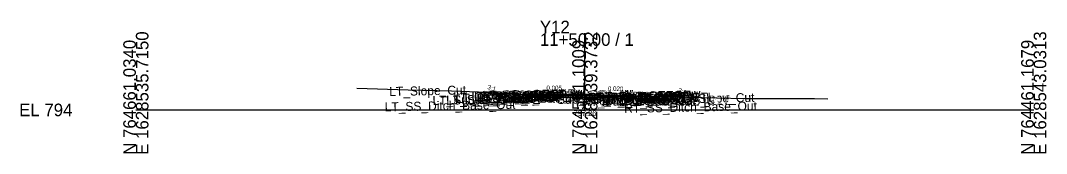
# Model space of a CAD drawing. Extents: x -26 to 203, y -10 to 3521.
# Drawn here: x -25.7 to 202.8, y 2990.3 to 3019.9 of the extents above; entities that cross this region are included whole.
import ezdxf

# ---------------------------------------------------------------- set-up
doc = ezdxf.new("R2010")
doc.units = 0
for name, color, linetype in [('Default', 7, 'Continuous'), ('Exist Cross Section Cell', 7, 'Continuous'), ('Exist XS Center Line Elevation Label', 7, 'Continuous'), ('Exist XS Ground Line', 7, 'Continuous'), ('Prop CMT Conc Surface', 7, 'Continuous'), ('Prop CMT Concrete Structures', 7, 'Continuous'), ('Prop CMT Pvmt Course 1', 7, 'Continuous'), ('Prop CMT Pvmt Course 2', 7, 'Continuous'), ('Prop CMT Pvmt Course 3', 7, 'Continuous'), ('Prop CMT Pvmt Surface', 7, 'Continuous'), ('Prop CMT Pvmt Wedge Surface 1', 7, 'Continuous'), ('Prop CMT Pvmt Wedge Surface 2', 7, 'Continuous'), ('Prop CMT Pvmt Wedge Surface 3', 7, 'Continuous'), ('Prop CMT Shld Paved Course 3', 7, 'Continuous'), ('Prop CMT Slope Grass', 7, 'Continuous'), ('Prop CMT Subgrade Earthwork', 7, 'Continuous'), ('Prop XS SE Text', 7, 'Continuous'), ('Prop XS Side Slope Text', 7, 'Continuous'), ('Scratch_Level_0', 7, 'Continuous')]:
    doc.layers.add(name, color=color, linetype=linetype)

msp = doc.modelspace()

# ---------------------------------------------------------------- linework, layer by layer
at = {"layer": 'Exist Cross Section Cell'}
for p, q in [((100, 3000), (100, 3017.06)), ((0, 3000), (100, 3000)), ((100, 3000), (200, 3000))]:
    msp.add_line(p, q, dxfattribs=at)
at = {"layer": 'Exist XS Ground Line'}
msp.add_lwpolyline([(49.23, 3004.87), (60.62, 3004.44), (70.29, 3004.23), (76.31, 3004.05), (86.64, 3003.46), (98.59, 3003.29), (100, 3003.26), (113.56, 3003.03), (117.92, 3002.97), (123.03, 3002.85), (135.64, 3002.51), (151.17, 3002.53), (154.14, 3002.48)], dxfattribs=at)
at = {"layer": 'Prop CMT Conc Surface'}
for points in [[(86.35, 3003.43), (85.35, 3003.35), (84.35, 3003.43)], [(113.73, 3003.09), (114.73, 3003), (115.73, 3003.09)]]:
    msp.add_lwpolyline(points, dxfattribs=at)
at = {"layer": 'Prop CMT Concrete Structures'}
for points in [[(86.35, 3003.43), (85.35, 3003.35), (84.35, 3003.43)], [(84.35, 3003.43), (84.35, 3002.85), (86.35, 3002.85)], [(86.35, 3002.85), (86.35, 3003.43)], [(113.73, 3003.09), (114.73, 3003), (115.73, 3003.09)], [(115.73, 3003.09), (115.73, 3002.5), (113.73, 3002.5)], [(113.73, 3002.5), (113.73, 3003.09)]]:
    msp.add_lwpolyline(points, dxfattribs=at)
at = {"layer": 'Prop CMT Pvmt Course 1'}
for points in [[(100, 3003.36), (86.35, 3003.43)], [(86.35, 3003.43), (86.35, 3003.18)], [(86.35, 3003.18), (100, 3003.11)], [(100, 3003.36), (87.35, 3003.43)], [(87.35, 3003.43), (87.35, 3003.3)], [(87.35, 3003.3), (100, 3003.23)], [(100, 3003.23), (100, 3003.36)], [(100, 3003.11), (100, 3003.36)], [(100, 3003.36), (112.73, 3003.11)], [(100, 3003.23), (100, 3003.36)], [(100, 3003.36), (113.73, 3003.09)], [(100, 3003.11), (100, 3003.36)], [(112.73, 3002.98), (100, 3003.23)], [(113.73, 3002.84), (100, 3003.11)], [(112.73, 3003.11), (112.73, 3002.98)], [(113.73, 3003.09), (113.73, 3002.84)]]:
    msp.add_lwpolyline(points, dxfattribs=at)
at = {"layer": 'Prop CMT Pvmt Course 2'}
for points in [[(100, 3003.11), (86.35, 3003.18)], [(86.35, 3003.18), (86.35, 3002.85)], [(100, 3002.78), (100, 3003.11)], [(100, 3002.78), (100, 3003.11)], [(100, 3003.11), (113.73, 3002.84)], [(86.35, 3002.85), (100, 3002.78)], [(113.73, 3002.5), (100, 3002.78)], [(113.73, 3002.84), (113.73, 3002.5)]]:
    msp.add_lwpolyline(points, dxfattribs=at)
at = {"layer": 'Prop CMT Pvmt Course 3'}
msp.add_line((115.73, 3002.5), (116.23, 3002.5), dxfattribs=at)
for points in [[(100, 3002.78), (86.35, 3002.85)], [(86.35, 3002.85), (86.35, 3002.52)], [(86.35, 3002.52), (87.35, 3002.51)], [(100, 3002.44), (100, 3002.78)], [(100, 3002.78), (113.73, 3002.5)], [(100, 3002.44), (100, 3002.78)], [(113.73, 3002.17), (112.73, 3002.19)], [(113.73, 3002.5), (113.73, 3002.17)]]:
    msp.add_lwpolyline(points, dxfattribs=at)
at = {"layer": 'Prop CMT Pvmt Surface'}
for points in [[(100, 3003.36), (86.35, 3003.43)], [(100, 3003.36), (87.35, 3003.43)], [(100, 3003.36), (113.73, 3003.09)], [(100, 3003.36), (112.73, 3003.11)]]:
    msp.add_lwpolyline(points, dxfattribs=at)
at = {"layer": 'Prop CMT Pvmt Wedge Surface 1'}
for points in [[(86.35, 3003.18), (86.35, 3003.43)], [(87.35, 3003.3), (87.35, 3003.43)], [(100, 3003.23), (87.35, 3003.3)], [(100, 3003.23), (112.73, 3002.98)], [(112.73, 3002.98), (112.73, 3003.11)], [(113.73, 3002.84), (113.73, 3003.09)]]:
    msp.add_lwpolyline(points, dxfattribs=at)
at = {"layer": 'Prop CMT Pvmt Wedge Surface 2'}
for points in [[(86.35, 3003.18), (86.35, 3003.43)], [(87.35, 3003.18), (87.35, 3003.43)], [(100, 3003.11), (87.35, 3003.18)], [(100, 3003.11), (100, 3003.36)], [(100, 3003.11), (100, 3003.36)], [(100, 3003.11), (100, 3003.36)], [(100, 3003.11), (100, 3003.36)], [(100, 3003.11), (112.73, 3002.86)], [(112.73, 3002.86), (112.73, 3003.11)], [(113.73, 3002.84), (113.73, 3003.09)]]:
    msp.add_lwpolyline(points, dxfattribs=at)
at = {"layer": 'Prop CMT Pvmt Wedge Surface 3'}
for points in [[(86.35, 3002.85), (86.35, 3003.43)], [(87.35, 3002.84), (87.35, 3003.43)], [(100, 3002.78), (100, 3003.36)], [(100, 3002.78), (100, 3003.36)], [(100, 3002.78), (100, 3003.36)], [(100, 3002.78), (100, 3003.36)], [(112.73, 3002.52), (112.73, 3003.11)], [(113.73, 3002.5), (113.73, 3003.09)], [(100, 3002.78), (87.35, 3002.84)], [(100, 3002.78), (112.73, 3002.52)]]:
    msp.add_lwpolyline(points, dxfattribs=at)
at = {"layer": 'Prop CMT Shld Paved Course 3'}
for p, q in [((83.51, 3002.51), (86.35, 3002.52)), ((116.57, 3002.16), (113.73, 3002.17))]:
    msp.add_line(p, q, dxfattribs=at)
for points in [[(86.35, 3002.85), (84.35, 3002.85), (83.85, 3002.85), (83.51, 3002.51)], [(113.73, 3002.5), (116.23, 3002.5), (116.23, 3002.5), (116.57, 3002.16)]]:
    msp.add_lwpolyline(points, dxfattribs=at)
at = {"layer": 'Prop CMT Slope Grass'}
for points in [[(84.35, 3003.43), (79.35, 3003.53), (78.09, 3003.95)], [(115.73, 3003.09), (120.73, 3003.19), (121.65, 3002.88)]]:
    msp.add_lwpolyline(points, dxfattribs=at)
at = {"layer": 'Prop CMT Subgrade Earthwork'}
for p, q in [((83.51, 3002.51), (82.55, 3003.47)), ((116.57, 3002.16), (117.53, 3003.12)), ((86.35, 3002.52), (83.51, 3002.51)), ((113.73, 3002.17), (116.57, 3002.16))]:
    msp.add_line(p, q, dxfattribs=at)
for points in [[(87.35, 3002.51), (87.37, 3003.45)], [(112.73, 3002.19), (112.71, 3003.05)], [(87.35, 3002.51), (86.35, 3002.52)], [(112.73, 3002.19), (113.73, 3002.17)]]:
    msp.add_lwpolyline(points, dxfattribs=at)

# ---------------------------------------------------------------- texts
at = {"layer": 'Default'}
msp.add_text('-', height=0.0001, dxfattribs=at).set_placement((0, 3000))
at = {"layer": 'Exist Cross Section Cell'}
for s, p in [('Y12', (90, 3017.06)), ('11+50.00 / 1', (90, 3014.26)), ('EL 794', (-26, 2998.6))]:
    msp.add_text(s, height=2.8, dxfattribs=at).set_placement(p)
for s, p in [('E 1628535.7150', (2.8, 2990)), ('E 1628539.3732', (102.8, 2990)), ('E 1628543.0313', (202.8, 2990)), ('N 764661.0340', (0, 2990)), ('N 764561.1009', (100, 2990)), ('N 764461.1679', (200, 2990))]:
    msp.add_text(s, height=2.8, rotation=90, dxfattribs=at).set_placement(p)
at = {"layer": 'Exist XS Center Line Elevation Label'}
msp.add_text('797.26', height=1.2, dxfattribs=at).set_placement((97.51, 2998.66))
at = {"layer": 'Prop XS SE Text'}
for s, rotation, p in [('0.005', 359.6967, (91.45, 3004.41)), ('0.020', 358.8542, (105.13, 3004.26))]:
    msp.add_text(s, height=1, rotation=rotation, dxfattribs=at).set_placement(p)
at = {"layer": 'Prop XS Side Slope Text'}
for p in [(78.21, 3004.7), (120.67, 3003.99)]:
    msp.add_text('3:1', height=1, rotation=341.5651, dxfattribs=at).set_placement(p)
at = {"layer": 'Scratch_Level_0'}
for s, p in [('LT_Slope_Cut', (56.46, 3003.1)), ('LT_Sub_OSS_DLT', (66.1, 3001.11)), ('LT_Sub_Trench_Out', (69.14, 3001.17)), ('LT_GS_OS_CTL', (70.74, 3001.82)), ('LT_PS3_Shelf_Out', (71.26, 3001.55)), ('LT_PV2_OEEOP_W', (74.79, 3001.93)), ('LT_PV3_OEEOP_W', (74.79, 3001.59)), ('LT_PV1_OEEOP_W', (75.36, 3002.06)), ('LT_PS3_OEOP', (76.02, 3001.64)), ('LT_PS2_OEOP', (76.36, 3001.98)), ('LT_Sub_OEOT', (76.45, 3001.32)), ('LT_PV2_OEOT', (76.55, 3001.99)), ('LT_PV3_OEOT', (76.55, 3001.65)), ('LT_PV1_OEOT', (77.11, 3002.25)), ('LT_PS1_OEOP', (77.18, 3002.25)), ('LT_PV1_OEEOP', (77.25, 3002.22)), ('RT_PV1_PGL_W', (89.86, 3002.03)), ('LT_PV1_PGL_W', (89.91, 3002.03)), ('Sub_PGL', (93.83, 3001.32)), ('PV2_PGL', (93.93, 3001.99)), ('PV3_PGL', (93.93, 3001.65)), ('PV1_PGL', (94.49, 3002.25)), ('RT_Sub_Trench_Out', (99.34, 3000.82)), ('RT_PV2_OEEOP_W', (100.12, 3001.6)), ('RT_PV3_OEEOP_W', (100.12, 3001.27)), ('RT_PV1_OEEOP_W', (100.69, 3001.74)), ('RT_PS3_Shelf_Out', (100.78, 3001.2)), ('RT_PV1_OEEOP', (102.58, 3001.9)), ('RT_Sub_OEOT', (103.78, 3000.97)), ('RT_PV2_OEOT', (103.88, 3001.64)), ('RT_PV3_OEOT', (103.88, 3001.3)), ('RT_PS2_OEOP', (104.19, 3001.63)), ('RT_PV1_OEOT', (104.44, 3001.9)), ('RT_PS1_OEOP', (104.5, 3001.9)), ('RT_PS3_OEOP', (104.53, 3001.29)), ('RT_GS_OS_CTL', (108.07, 3001.47)), ('RT_Sub_OSS_DLT', (108.79, 3000.76)), ('RT_Slope_Cut', (120.26, 3001.44)), ('LT_SS_Ditch_Base_Out', (55.45, 2999.67)), ('RT_SS_Ditch_Base_Out', (108.78, 2999.33))]:
    msp.add_text(s, height=2, rotation=1.1458, dxfattribs=at).set_placement(p)

doc.saveas('drawing.dxf')
